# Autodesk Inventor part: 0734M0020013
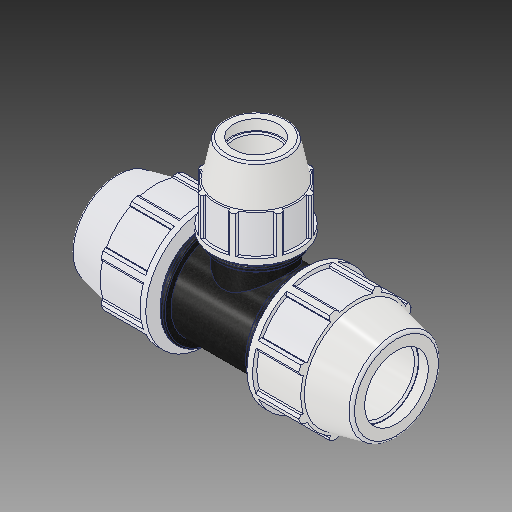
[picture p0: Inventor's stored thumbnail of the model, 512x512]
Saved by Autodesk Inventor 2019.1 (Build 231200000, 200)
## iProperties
Created: 2017-02
Part Number: 0734M0020013
Material: PVC-Piping
Description: PLASSON REDUCING TEE 2'' - 1 1/4'' - 2''
Document SubType Name: Modeling
Designer: KIM
Mass: 92.6774 g
Surface Area: 199.44 cm^2
Volume: 66.1981 cm^3
Density: 1.4 g/cm^3
Appearance: PTFE
Author: Кирилл
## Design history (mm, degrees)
derived "0734M0.ipt"
feature "Solid1::0734M0.ipt"
feature "Solid2::0734M0.ipt"
tag "TaggingFeature1"
body "Solid1"
other parameters: "d2" = 60.1, "d4" = 11.08075, "d5" = 37.23132, "d7" = 113.03, "d11" = 4.4323, "d13" = 120 deg, "d14" = 84.14, "d15" = 12 deg, "d16" = 98.3361, "d18" = 3.005, "d19" = 35 deg, "d20" = 17.5 deg, "d21" = 105.1179, "d23" = 0, "d25" = 360 deg, "d27" = 2.2606, "d33" = 1.202, "d42" = 47.86884, "d43" = 3.3909, "d46" = 1.803, "d67" = 84.7725, "d76" = 42.1, "d77" = 82.042, "d78" = 12 deg, "d79" = 138.938, "d80" = 120 deg, "d81" = 58.94, "d82" = 11.57817, "d87" = 4.63127, "d89" = 34.7345, "d90" = 41.6814, "d96" = 22.1615, "d98" = 76.29906, "d99" = 35 deg, "d100" = 17.5 deg, "d102" = 0, "d103" = 1.64084, "d107" = 360 deg, "d109" = 1.263, "d112" = 2.105, "d113" = 5.46947, "d114" = 0, "d117" = 265.938, "d118" = 71.37654, "d126" = 54.09, "d127" = 112.014, "d131" = 5.55752, "d132" = 37.89, "d133" = 84.074, "d135" = 0, "d138" = 5.31876, "d143" = 0, "d148" = 61.5315, "d168" = 54.09, "d170" = 0, "d171" = 42.1, "d173" = 0, "d176" = 5.46947, "d177" = 0, "d_" = 60.1, "E_" = 113.03, "A_" = 138.938, "l_" = 112.014, "E_1" = 82.042, "l_1" = 84.074, "d_1" = 42.1, "H_" = 265.938
